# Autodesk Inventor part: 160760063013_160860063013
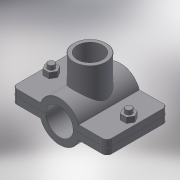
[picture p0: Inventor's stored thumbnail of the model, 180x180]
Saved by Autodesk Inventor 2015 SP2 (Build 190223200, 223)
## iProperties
Created: 2017-05
Part Number: 160760063013_160860063013
Material: Generic
Description: PLASSON SADDLE 63-1.1/4"
Document SubType Name: Modeling
Designer: KIM
Density: 1 g/cm^3
Appearance: Default
Author: KIM
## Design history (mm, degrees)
derived "16076.ipt"
feature "Solid1::16076.ipt"
feature "Solid2::16076.ipt"
tag "TaggingFeature1"
body "Solid1"
other parameters: "d0" = 78.75, "d1" = 116, "d2" = 31.5, "d3" = 63, "d4" = 84, "d5" = 0, "d6" = 5.8, "d7" = 116, "d8" = 0.1, "d10" = 0, "d11" = 0.63, "d14" = 50.6376, "d20" = 0.63, "d23" = 0.63, "d37" = 8, "d38" = 39.5, "d39" = 0, "d40" = 3, "d41" = 5, "d42" = 0, "d43" = 6, "d44" = 3, "d45" = 0, "d46" = 0.63, "d51" = 66, "d52" = 38.952, "d53" = 25, "d54" = 0, "d55" = 32, "d57" = 0, "d58" = 68.04, "d60" = 0, "d63" = 8, "d66" = 68, "d_" = 63, "B_" = 32, "G_" = 38.952, "A_" = 66, "L_" = 116, "L_1" = 84, "l_2" = 25
